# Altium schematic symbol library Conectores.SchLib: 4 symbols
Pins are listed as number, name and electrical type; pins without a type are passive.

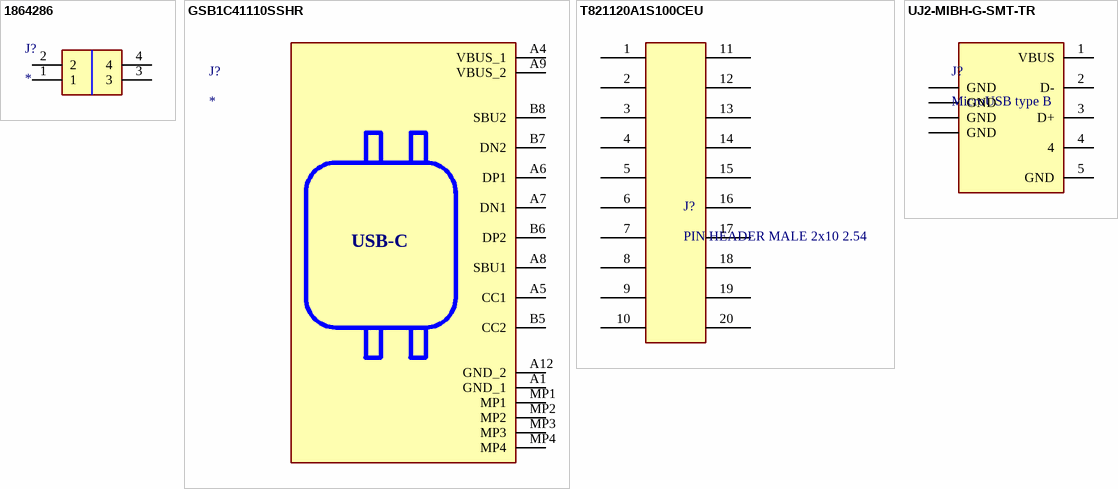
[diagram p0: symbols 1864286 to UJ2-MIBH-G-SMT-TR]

## 1864286
designator J?
Connector; Manufacturer_Name: Phoenix Contact; Manufacturer_Part_Number: 1864286
footprint 1864286
pins: 1, 2, 3, 4

## GSB1C41110SSHR
designator J?
Connector; Manufacturer_Name: Amphenol Communications Solutions; Manufacturer_Part_Number: GSB1C41110SSHR
footprint GSB1C41110SSHR
pins: A1 GND_1, A4 VBUS_1, A5 CC1, A6 DP1, A7 DN1, A8 SBU1, A9 VBUS_2, A12 GND_2, B5 CC2, B6 DP2, B7 DN2, B8 SBU2, MP1, MP2, MP3, MP4

## T821120A1S100CEU
designator J?, comment PIN HEADER MALE 2x10 2.54
PIN HEADER MALE 2x10 2.54 TH; Manufacturer_Name: Amphenol; Manufacturer_Part_Number: T821120A1S100CEU
footprint SHDR20W64P254X254_2X10_3302X895X915P
pins: 1, 2, 3, 4, 5, 6, 7, 8, 9, 10, 11, 12, 13, 14, 15, 16, 17, 18, 19, 20

## UJ2-MIBH-G-SMT-TR
designator J?, comment MicroUSB type B
Manufacturer_Name: Same Sky; Manufacturer_Part_Number: UJ2-MIBH-G-SMT-TR
footprint UJ2MIBHGSMTTR
pins: 1 VBUS, 2 D-, 3 D+, 4, 5 GND, MP1 GND, MP2 GND, MP3 GND, MP4 GND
